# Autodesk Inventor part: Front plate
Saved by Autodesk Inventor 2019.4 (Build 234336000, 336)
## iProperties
Created: 2020-04
Part Number: Front plate
Material: Generic
Document SubType Name: Modeling
Designer: Administrator
Density: 1 g/cm^3
Appearance: Default
Title: Front plate v3
Author: Administrator
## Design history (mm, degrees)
feature "Body1"
body "Solid1"
